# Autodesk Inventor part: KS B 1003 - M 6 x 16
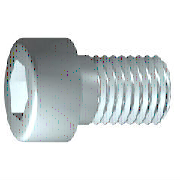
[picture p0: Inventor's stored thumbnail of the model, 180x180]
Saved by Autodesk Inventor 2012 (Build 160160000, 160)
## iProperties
Created: 2009-02
Part Number: KS B 1003 - M 6 x 16
Material: Steel, Mild
Description: 6각머리 태핑 나사
Document SubType Name: Modeling
Standard: KS B 1003
Designer: KYOUNG IL JANG
Standards Organization: KS
Language: ko-KR
Size Designation: M 6 x 16
Categories: <MemberInstance><Categories><Category DisplayName="조임쇠" InternalName="e4da775c-781d-43d5-af7c-5136215cf5a6" Mnemonic="FSTN"><Category DisplayName="볼트" InternalN
Density: 7.86 g/cm^3
Mass: 6.59379 g
Surface Area: 6.88703 cm^2
Volume: 0.838904 cm^3
Company: 한국ATC센터
IsCustomPart: 0
Author: KYOUNG IL JANG
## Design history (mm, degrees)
workplane "Work Plane1"
fillet "Fillet2" dims "d30" = 0.1 (= R)
revolve "본체" stored, may be unused: angle "d10" = 90 deg
sketch "스케치2"
  geometry: L1 (0, -7)-(0, 7) reference; L2 (-7, 0)-(7, 0) reference; L3 (2.887, 0)-(1.443, -2.5); L4 (1.443, -2.5)-(-1.443, -2.5); L5 (-1.443, -2.5)-(-2.887, 0); L6 (-2.887, 0)-(-1.443, 2.5); L7 (-1.443, 2.5)-(1.443, 2.5); L8 (1.443, 2.5)-(2.887, 0); 2 further points
  constraints: 12 end point, 1 coincident, 1 horizontal alignment, 1 point on line, 12 other
extrude "슬롯" join sketch "스케치2" stored distance "d11" = 10; taper "d12" = 0 deg
body "Solid1"
fillet "모깎기1" dims "d17" = 0.6 (= RR)
feature "스레드" dims "d13" = 13.5 (= GEL), "d14" = 0
chamfer "모따기1" distance "d15" = 0.61345 (= -0.5 x SPD + 0.5 x GD); stored, may be unused: second distance "d16" = 0.61345 (= GUL), angle "d27" = 45 deg
sketch "스케치1"
  geometry: L1 (-1.333, 0)-(16, 0); L2 (16, 0)-(16, 3); L3 (16, 3)-(2.5, 3); L4 (2.5, 3)-(1.886, 3); L5 (1.886, 3)-(0, 3); L6 (0, 3)-(0, 5); L7 (0, 5)-(-6, 5); L8 (-6, 5)-(-6, 2.887); L9 (-6, 2.887)-(-3, 2.887); L10 (-3, 2.887)-(-1.333, 0); L11 (-10.4, 0)-(20.4, 0) reference; L12 (0, -1)-(0, 6) reference; L13 (2.5, 3)-(0, 3)
  constraints: 22 end point, 6 parallel, 2 collinear, 2 perpendicular, 1 horizontal, 1 point on line
  dimensions: "d1" = 13.5 distance from line of L3.end L2 (= GEL); "d2" = 0.61355 distance of L4.end L3.end (computed from GAL); "d3" = 6 distance between parallel lines of L8 L6 (= KOH); "d4" = 3 distance of L8.end L9.end (= INTI); "d5" = 60 deg angle of L10 L1; "d6" = 6 diameter of L3 L1 (= GD); "d7" = 6 diameter of L5 L1 (= BDM); "d8" = 5.7735 diameter of L9 L1 (= 1.1547 x SW); "d9" = 10 diameter of L7 L1 (= KOD); "d26" = 16 distance between parallel lines of L12 L2 (= NLG)
other parameters: "GD" = 6 (= NND) [user parameter; used in 2 equation terms], "NLG" = 16 [user parameter; used in 1 equation term], "GEL" = 13.5 [user parameter; used in 2 equation terms], "KOD" = 10 [user parameter; used in 1 equation term], "KOH" = 6 [user parameter; used in 1 equation term], "INTI" = 3 [user parameter; used in 1 equation term], "GAL" = 0.61345 (= 0.61345 x PTC) [user parameter; used in 1 equation term], "GUL" = 0.61345 (= 0.61345 x PTC) [user parameter; used in 1 equation term], "BDM" = 6 (= NND) [user parameter; used in 1 equation term], "SW" = 5 [user parameter; used in 2 equation terms], "RR" = 0.6 [user parameter; used in 1 equation term], "SPD" = 4.7731 (= NND - 1.2269 x PTC) [user parameter; used in 1 equation term], "d19" = 0, "d28" = 0, "d29" = 0, "R" = 0.1 [user parameter; used in 1 equation term], "PHH" = 0.25 [user parameter], "GD1" = 4.7731 (= THREADDIA - 1.2269 x PTC) [user parameter], "THREADDIA" = 6 [user parameter; used in 1 equation term], "FAWI" = 45 deg [user parameter], "PTC" = 1 [user parameter; used in 5 equation terms], "NND" = 6 [user parameter; used in 3 equation terms], "TOA" = 30 deg [user parameter], "E0" = 5.775 (= 1.155 x SW) [user parameter]
